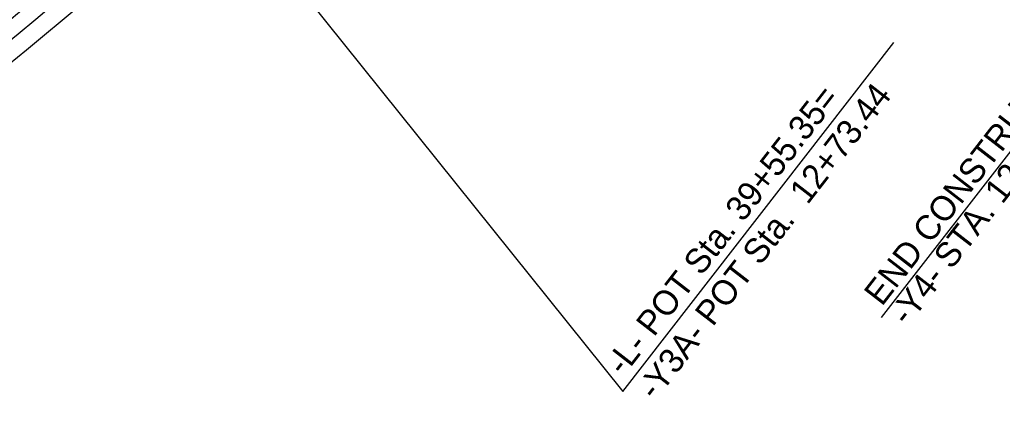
# Model space of a CAD drawing. Extents: x 2010838 to 2015151, y 441905 to 447792.
# Drawn here: x 2014077.9 to 2014355.7, y 445077.6 to 445187.3 of the extents above; entities that cross this region are included whole.
import ezdxf

# ---------------------------------------------------------------- set-up
doc = ezdxf.new("R2010")
doc.units = 0
for name, color, linetype in [('C-Grave Plots', 7, 'Continuous'), ('CLRD', 7, 'Continuous'), ('Default_10ft_LIDAR_Contou', 7, 'Continuous'), ('HATCH', 7, 'Continuous'), ('S-Existing Minor', 7, 'Continuous'), ('S-overhead electric', 7, 'Continuous'), ('TEXT-LG', 7, 'Continuous'), ('TEXT-MED', 7, 'Continuous')]:
    doc.layers.add(name, color=color, linetype=linetype)

msp = doc.modelspace()

# ---------------------------------------------------------------- linework, layer by layer
at = {"layer": 'CLRD'}
msp.add_arc((2013223.9, 446217.91), 1300, 266.62643, 322.2051, dxfattribs=at)
at = {"layer": 'Default_10ft_LIDAR_Contou'}
for p, q in [((2014104.53, 445261.61), (2014248.47, 445082.05)), ((2014248.47, 445082.05), (2014325.08, 445180.83))]:
    msp.add_line(p, q, dxfattribs=at)
at = {"layer": 'HATCH'}
for radius, start, end in [(1279.25, 293.04012, 322.2051), (1320.75, 278.35841, 312.84627)]:
    msp.add_arc((2013223.9, 446217.91), radius, start, end, dxfattribs=at)
at = {"layer": 'S-Existing Minor'}
msp.add_line((2014383.76, 445183.22), (2014321.53, 445102.99), dxfattribs=at)
at = {"layer": 'S-overhead electric'}
msp.add_arc((2013223.9, 446217.91), 1334.75, 295.78264, 312.84627, dxfattribs=at)
at = {"layer": 'TEXT-LG'}
for radius, start in [(1341.25, 295.13795), (1346.25, 294.89421)]:
    msp.add_arc((2013223.9, 446217.91), radius, start, 312.84627, dxfattribs=at)
at = {"layer": 'TEXT-MED'}
msp.add_arc((2013223.9, 446217.91), 1336.75, 295.78264, 312.84627, dxfattribs=at)

# ---------------------------------------------------------------- texts
at = {"layer": 'C-Grave Plots'}
for s, p in [('END CONSTRUCTION', (2014321.69, 445105.93)), ('-Y4- STA. 12+00.00', (2014328.95, 445100.31))]:
    msp.add_text(s, height=7, rotation=52.2051, dxfattribs=at).set_placement(p)
at = {"layer": 'Default_10ft_LIDAR_Contou'}
for s, p in [('-L- POT Sta. 39+55.35=', (2014248.63, 445086.19)), ('-Y3A- POT Sta.  12+73.44', (2014257.62, 445079.22))]:
    msp.add_text(s, height=7, rotation=52.2051, dxfattribs=at).set_placement(p)

doc.saveas('drawing.dxf')
